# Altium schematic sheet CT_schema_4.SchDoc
size 339 x 183 mm
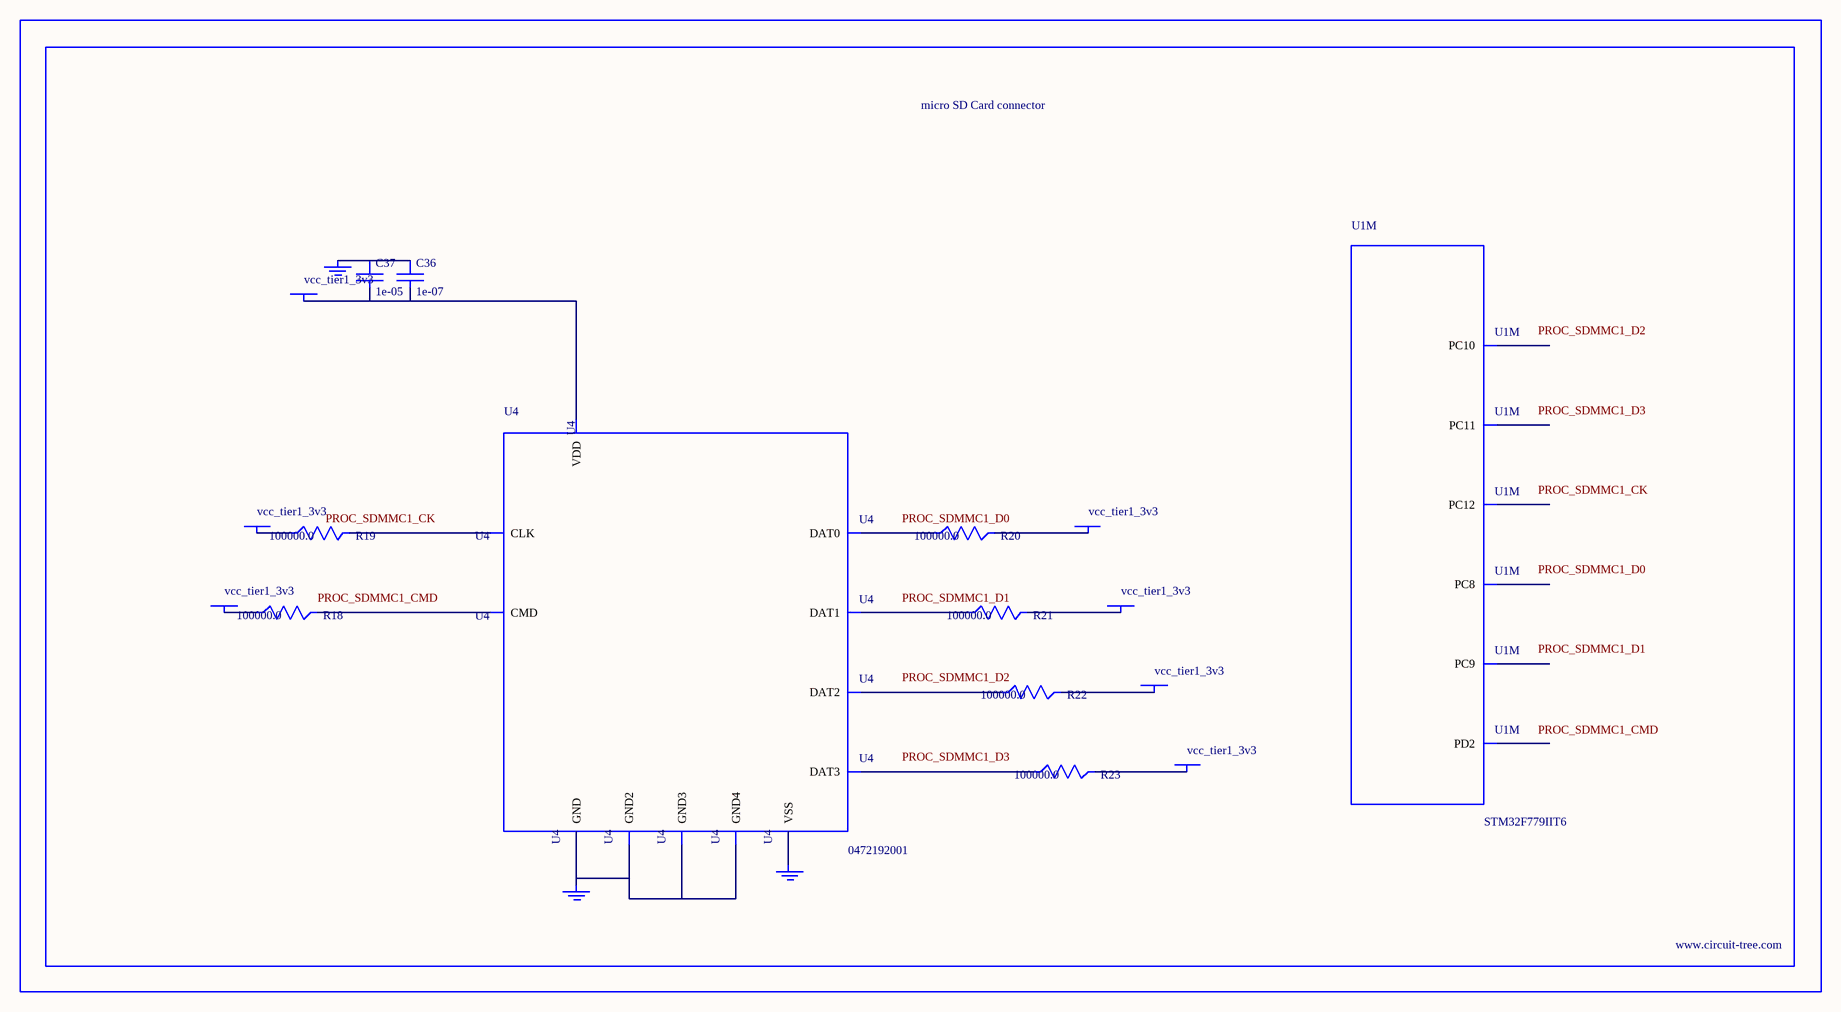
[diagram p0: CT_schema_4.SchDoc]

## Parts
BORDER3  (no value)
C36  1e-07  [C0402]
C37  1e-05  [C0805]
GND_INSTANCE_3_0  (no value)
GND_INSTANCE_3_1  (no value)
GND_INSTANCE_3_2  (no value)
POWER_INSTANCE_3_0  vcc_tier1_3v3
POWER_INSTANCE_3_1  vcc_tier1_3v3
POWER_INSTANCE_3_2  vcc_tier1_3v3
POWER_INSTANCE_3_3  vcc_tier1_3v3
POWER_INSTANCE_3_4  vcc_tier1_3v3
POWER_INSTANCE_3_5  vcc_tier1_3v3
POWER_INSTANCE_3_6  vcc_tier1_3v3
R18  100000.0  [R0603]
R19  100000.0  [R0603]
R20  100000.0  [R0603]
R21  100000.0  [R0603]
R22  100000.0  [R0603]
R23  100000.0  [R0603]
U1  STM32F779IIT6  [LQFP176]  (part M of 14)
U4  0472192001  [MOLEX_47219-2001]

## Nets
NetC36_1: C36.1 C37.1 GND_INSTANCE_3_0.0(GND)
NetC36_2: C36.2 C37.2 POWER_INSTANCE_3_3.0(PWR) U4.4(VDD)
NetGND_INSTANCE_3_1_0: GND_INSTANCE_3_1.0(GND) U4.6(VSS)
NetGND_INSTANCE_3_2_0: GND_INSTANCE_3_2.0(GND) U4.G1(GND) U4.G2(GND2) U4.G3(GND3) U4.G4(GND4)
NetPOWER_INSTANCE_3_0_0: POWER_INSTANCE_3_0.0(PWR) R22.2
NetPOWER_INSTANCE_3_1_0: POWER_INSTANCE_3_1.0(PWR) R23.2
NetPOWER_INSTANCE_3_2_0: POWER_INSTANCE_3_2.0(PWR) R18.1
NetPOWER_INSTANCE_3_4_0: POWER_INSTANCE_3_4.0(PWR) R19.1
NetPOWER_INSTANCE_3_5_0: POWER_INSTANCE_3_5.0(PWR) R20.2
NetPOWER_INSTANCE_3_6_0: POWER_INSTANCE_3_6.0(PWR) R21.2
NetR18_2: R18.2 U4.3(CMD)
NetR19_2: R19.2 U4.5(CLK)
NetR20_1: R20.1 U4.7(DAT0)
NetR21_1: R21.1 U4.8(DAT1)
NetR22_1: R22.1 U4.1(DAT2)
NetR23_1: R23.1 U4.2(DAT3)

Not connected (* = marked no-connect by the designer): U1 121(PC8) 122(PC9) 139(PC10) 140(PC11) 141(PC12) 144(PD2)

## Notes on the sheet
- Labels drawn without touching a wire or pin: PROC_SDMMC1_CK, PROC_SDMMC1_CMD, PROC_SDMMC1_D0, PROC_SDMMC1_D1, PROC_SDMMC1_D2, PROC_SDMMC1_D3

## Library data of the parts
BORDER3 = BORDER_PAGE3
C36 = C0402C104K3RACTU
C37 = C0805C106K8RACTU
GND_INSTANCE_3_0-GND_INSTANCE_3_2 = GND
POWER_INSTANCE_3_0-POWER_INSTANCE_3_6 = PWR
R18-R23 = RC0603JR-07100KL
